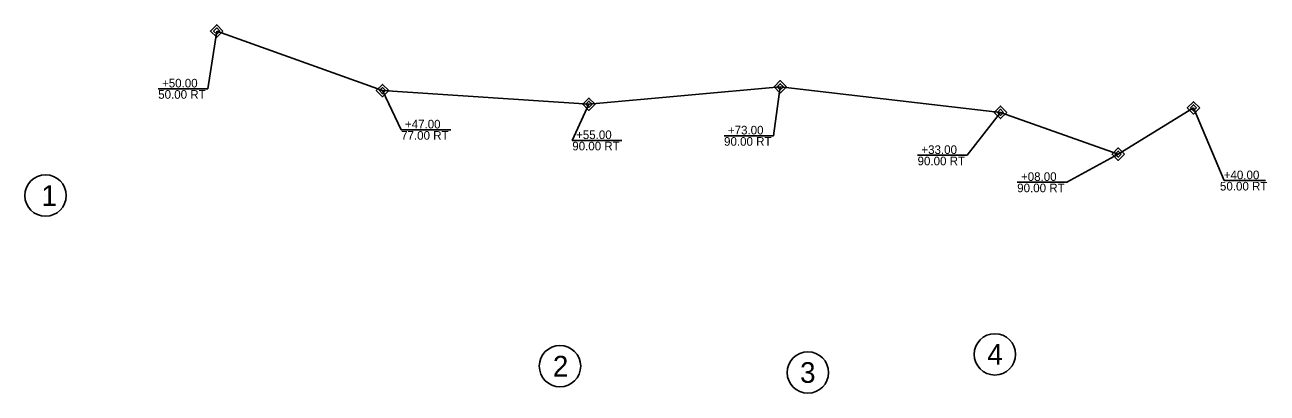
# Model space of a CAD drawing. Extents: x 1002576 to 1014655, y 551673 to 557994.
# Drawn here: x 1009571 to 1010291, y 552252 to 552465 of the extents above; entities that cross this region are included whole.
import ezdxf

# ---------------------------------------------------------------- set-up
doc = ezdxf.new("R2010")
doc.units = 0
for name, color, linetype in [('Exist Hydro Stream or Body of Water', 7, 'Continuous'), ('Exist Other Culture Area Outline', 7, 'Continuous'), ('Exist Roads EOP Other', 7, 'Continuous'), ('Exist Structure Major Deck Tunnel Box Culvert', 7, 'Continuous'), ('Exist Utilities Power Pole CELL', 7, 'Continuous')]:
    doc.layers.add(name, color=color, linetype=linetype)

msp = doc.modelspace()

# ---------------------------------------------------------------- linework, layer by layer
at = {"layer": 'Exist Hydro Stream or Body of Water'}
for p, q in [((1009681.94, 552461.74), (1009681.94, 552461.74)), ((1009778.01, 552427.17), (1009778.01, 552427.17)), ((1010008.55, 552429.34), (1010008.55, 552429.34)), ((1009897.65, 552419.26), (1009897.65, 552419.26)), ((1010136.12, 552414.56), (1010136.12, 552414.56)), ((1010247.95, 552417.15), (1010247.95, 552417.15)), ((1010204.35, 552390.27), (1010204.35, 552390.27))]:
    msp.add_line(p, q, dxfattribs=at)
at = {"layer": 'Exist Other Culture Area Outline'}
for p, q in [((1009681.94, 552461.74), (1009778.01, 552427.17)), ((1009778.01, 552427.17), (1009897.65, 552419.26)), ((1009897.65, 552419.26), (1010008.55, 552429.34)), ((1010008.55, 552429.34), (1010136.12, 552414.56)), ((1010136.12, 552414.56), (1010204.35, 552390.27)), ((1010204.35, 552390.27), (1010247.95, 552417.15))]:
    msp.add_line(p, q, dxfattribs=at)
at = {"layer": 'Exist Roads EOP Other'}
for p, q in [((1009676.78, 552428.22), (1009648.08, 552428.22)), ((1009817.54, 552404.45), (1009788.84, 552404.45)), ((1009916.71, 552398.28), (1009888.01, 552398.28)), ((1010004.68, 552400.96), (1009975.97, 552400.96)), ((1010116.81, 552389.62), (1010088.11, 552389.62)), ((1010289.7, 552374.98), (1010265.66, 552374.98)), ((1010174.54, 552373.98), (1010145.83, 552373.98))]:
    msp.add_line(p, q, dxfattribs=at)
for points in [[(1009676.78, 552428.22), (1009681.94, 552461.74)], [(1009788.84, 552404.45), (1009778.01, 552427.17)], [(1010004.68, 552400.96), (1010008.55, 552429.34)], [(1009888.01, 552398.28), (1009897.65, 552419.26)], [(1010116.81, 552389.62), (1010136.12, 552414.56)], [(1010265.66, 552374.98), (1010247.95, 552417.15)], [(1010174.54, 552373.98), (1010204.35, 552390.27)]]:
    msp.add_lwpolyline(points, dxfattribs=at)
at = {"layer": 'Exist Structure Major Deck Tunnel Box Culvert'}
for points in [[(1009685.54, 552461.74), (1009681.94, 552458.14), (1009678.34, 552461.74), (1009681.94, 552465.34)], [(1009683.74, 552461.74), (1009681.94, 552459.94), (1009680.14, 552461.74), (1009681.94, 552463.54)], [(1010012.15, 552429.34), (1010008.55, 552425.74), (1010004.95, 552429.34), (1010008.55, 552432.94)], [(1009781.61, 552427.17), (1009778.01, 552423.57), (1009774.41, 552427.17), (1009778.01, 552430.77)], [(1009779.81, 552427.17), (1009778.01, 552425.37), (1009776.21, 552427.17), (1009778.01, 552428.97)], [(1010010.35, 552429.34), (1010008.55, 552427.54), (1010006.75, 552429.34), (1010008.55, 552431.14)], [(1009901.25, 552419.26), (1009897.65, 552415.66), (1009894.05, 552419.26), (1009897.65, 552422.86)], [(1009899.45, 552419.26), (1009897.65, 552417.46), (1009895.85, 552419.26), (1009897.65, 552421.06)], [(1010139.71, 552414.56), (1010136.11, 552410.96), (1010132.52, 552414.56), (1010136.11, 552418.16)], [(1010251.55, 552417.15), (1010247.95, 552413.55), (1010244.35, 552417.15), (1010247.95, 552420.75)], [(1010249.75, 552417.15), (1010247.95, 552415.35), (1010246.15, 552417.15), (1010247.95, 552418.95)], [(1010137.91, 552414.56), (1010136.11, 552412.76), (1010134.32, 552414.56), (1010136.11, 552416.36)], [(1010207.95, 552390.27), (1010204.35, 552386.67), (1010200.75, 552390.27), (1010204.35, 552393.87)], [(1010206.15, 552390.27), (1010204.35, 552388.47), (1010202.55, 552390.27), (1010204.35, 552392.07)]]:
    msp.add_lwpolyline(points, close=True, dxfattribs=at)
at = {"layer": 'Exist Utilities Power Pole CELL'}
for p, q in [((1009582.77, 552366.28), (1009582.77, 552366.28)), ((1010132.87, 552274.13), (1010132.87, 552274.13)), ((1009880.86, 552267.29), (1009880.86, 552267.29)), ((1010024.5, 552263.61), (1010024.5, 552263.61))]:
    msp.add_line(p, q, dxfattribs=at)
for centre in [(1009582.77, 552366.28), (1010132.87, 552274.13), (1009880.86, 552267.29), (1010024.5, 552263.61)]:
    msp.add_circle(centre, 12, dxfattribs=at)

# ---------------------------------------------------------------- texts
at = {"layer": 'Exist Roads EOP Other'}
for s, p in [('+50.00', (1009650.26, 552429)), ('50.00 RT', (1009648.05, 552422.44)), ('77.00 RT', (1009788.81, 552398.67)), ('+47.00', (1009791.02, 552405.22)), ('+55.00', (1009890.19, 552399.05)), ('+73.00', (1009978.16, 552401.73)), ('90.00 RT', (1009887.99, 552392.5)), ('90.00 RT', (1009975.95, 552395.18)), ('+33.00', (1010090.29, 552390.4)), ('90.00 RT', (1010088.08, 552383.84)), ('+08.00', (1010148.01, 552374.76)), ('+40.00', (1010265.51, 552375.76)), ('90.00 RT', (1010145.81, 552368.2)), ('50.00 RT', (1010263.31, 552369.21))]:
    msp.add_text(s, height=5, dxfattribs=at).set_placement(p)
at = {"layer": 'Exist Utilities Power Pole CELL'}
for s, p in [('1', (1009580.4, 552360.28)), ('4', (1010128.46, 552268.13)), ('2', (1009876.77, 552261.29)), ('3', (1010020.01, 552257.61))]:
    msp.add_text(s, height=12, dxfattribs=at).set_placement(p)

doc.saveas('drawing.dxf')
